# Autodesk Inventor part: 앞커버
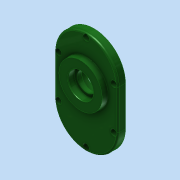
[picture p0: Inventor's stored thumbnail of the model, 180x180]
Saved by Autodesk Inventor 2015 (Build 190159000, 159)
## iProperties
Created: 2016-12
Part Number: 앞커버
Material: 알루미늄 6061
Document SubType Name: Modeling
Designer: mduedu
Density: 2.71 g/cm^3
Appearance: 매끄러움 - 짙은 산림 녹색
Mass: 264.67 g
Surface Area: 264.413 cm^2
Volume: 97.664 cm^3
Author: mduedu
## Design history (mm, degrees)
sketch "스케치1"
  geometry: L1 (40, -25)-(40, 25); L2 (-40, 25)-(-40, -25); L3 (-40, -25)-(40, 25); L4 (40, -25)-(-40, 25); A1 r 40 centre (0, 25) between (40, 25) and (-40, 25); A2 r 40 centre (0, -25) between (-40, -25) and (40, -25); 1 further point
  constraints: 8 end point, 4 point on circle, 4 tangent, 2 centre point, 2 midpoint, 1 parallel, 1 vertical
  dimensions: "d0" = 130 dimension on A2 A1; "d2" = 80 distance between parallel lines of L1 L2
extrude "돌출1" new body sketch "스케치1" distance "d3" = 10; taper "d4" = 0 deg
sketch "스케치2"
  geometry: C1 r 21 at (0, 11); 1 further point
  constraints: 1 centre point, 1 vertical alignment
  dimensions: "d5" = 42 diameter of C1; "d7" = 11 distance of C1.centre point (0, 0)
extrude "돌출2" join sketch "스케치2" distance "d8" = 7; taper "d9" = 0 deg
sketch "스케치3"
  geometry: C1 r 15 at (0, -33.1); C2 r 21 at (0, 11) reference; 1 further point
  constraints: 1 centre point, 1 vertical alignment
  dimensions: "d10" = 30 diameter of C1; "d71" = 44.1 distance of C1.centre C2.centre
extrude "돌출3" join sketch "스케치3" distance "d12" = 7; taper "d13" = 0 deg
sketch "스케치4"
  geometry: C1 r 28 at (0, 11); A1 r 21 centre (0, 11) between (8.978, -7.984) and (-8.978, -7.984) reference; 1 further point
  constraints: 1 centre point, 1 coincident
  dimensions: "d14" = 56 diameter of C1
extrude "돌출4" join sketch "스케치4" distance "d15" = 7; taper "d16" = -5 deg
hole "구멍1" diameter "d19" = 35; stored, may be unused: countersink angle "d23" = 90 deg, drill point angle "d25" = 0 deg; dims "d17" = 10, "d18" = 10, "d20" = 6, "d21" = 4, "d22" = 2, "d24" = 10
hole "구멍2" diameter "d28" = 22; stored, may be unused: countersink angle "d32" = 90 deg, drill point angle "d34" = 0 deg; dims "d26" = 10, "d27" = 10, "d29" = 6, "d30" = 4, "d31" = 2, "d33" = 7
hole "구멍3" diameter "d37" = 19; stored, may be unused: countersink angle "d41" = 90 deg, drill point angle "d43" = 0 deg; dims "d35" = 10, "d36" = 10, "d38" = 6, "d39" = 4, "d40" = 2, "d42" = 1
hole "구멍4" diameter "d46" = 32; stored, may be unused: countersink angle "d50" = 90 deg, drill point angle "d52" = 0 deg; dims "d47" = 6, "d48" = 4, "d49" = 2, "d51" = 8.3, "d89" = 10, "d90" = 10
hole "구멍5" diameter "d55" = 25; stored, may be unused: countersink angle "d59" = 90 deg, drill point angle "d61" = 0 deg; dims "d53" = 10, "d54" = 10, "d56" = 6, "d57" = 4, "d58" = 2, "d60" = 8
fillet "모깎기1" dims "d62" = 0.3
fillet "모깎기2" dims "d63" = 2
chamfer "모따기1" distance "d64" = 1; stored, may be unused: second distance "d65" = 2, angle "d66" = 45 deg
chamfer "모따기2" distance "d91" = 0.8; stored, may be unused: second distance "d92" = 2, angle "d93" = 30 deg
fillet "모깎기4" dims "d68" = 2
fillet "모깎기5" dims "d69" = 0.3
fillet "모깎기6" dims "d70" = 2
sketch "스케치5"
  geometry: L1 (-40, 25)-(-40, -25) reference; L2 (40, -25)-(40, 25) reference; L3 (35, 25)-(35, -25); L4 (-35, -25)-(-35, 25); A1 r 40 centre (0, 25) between (40, 25) and (-40, 25) reference; A2 r 40 centre (0, -25) between (-40, -25) and (40, -25) reference; A3 r 35 centre (0, 25) between (35, 25) and (-35, 25); A4 r 35 centre (0, -25) between (-35, -25) and (35, -25); 2 further points
  constraints: 5 point on circle, 4 end point, 2 centre point, 1 vertical alignment, 3 other
  dimensions: "d72" = 5 distance between parallel lines of L2 L3
sketch "스케치7"
  geometry: 1 further point
  constraints: 1 other
hole "구멍7" sketch "스케치7" at (0, 60) diameter "d80" = 4.5; stored, may be unused: countersink angle "d84" = 90 deg, drill point angle "d86" = 0 deg; dims "d81" = 6, "d82" = 8, "d83" = 4.6, "d85" = 8
node "솔리드1"
pattern_linear "직사각형 패턴1"
